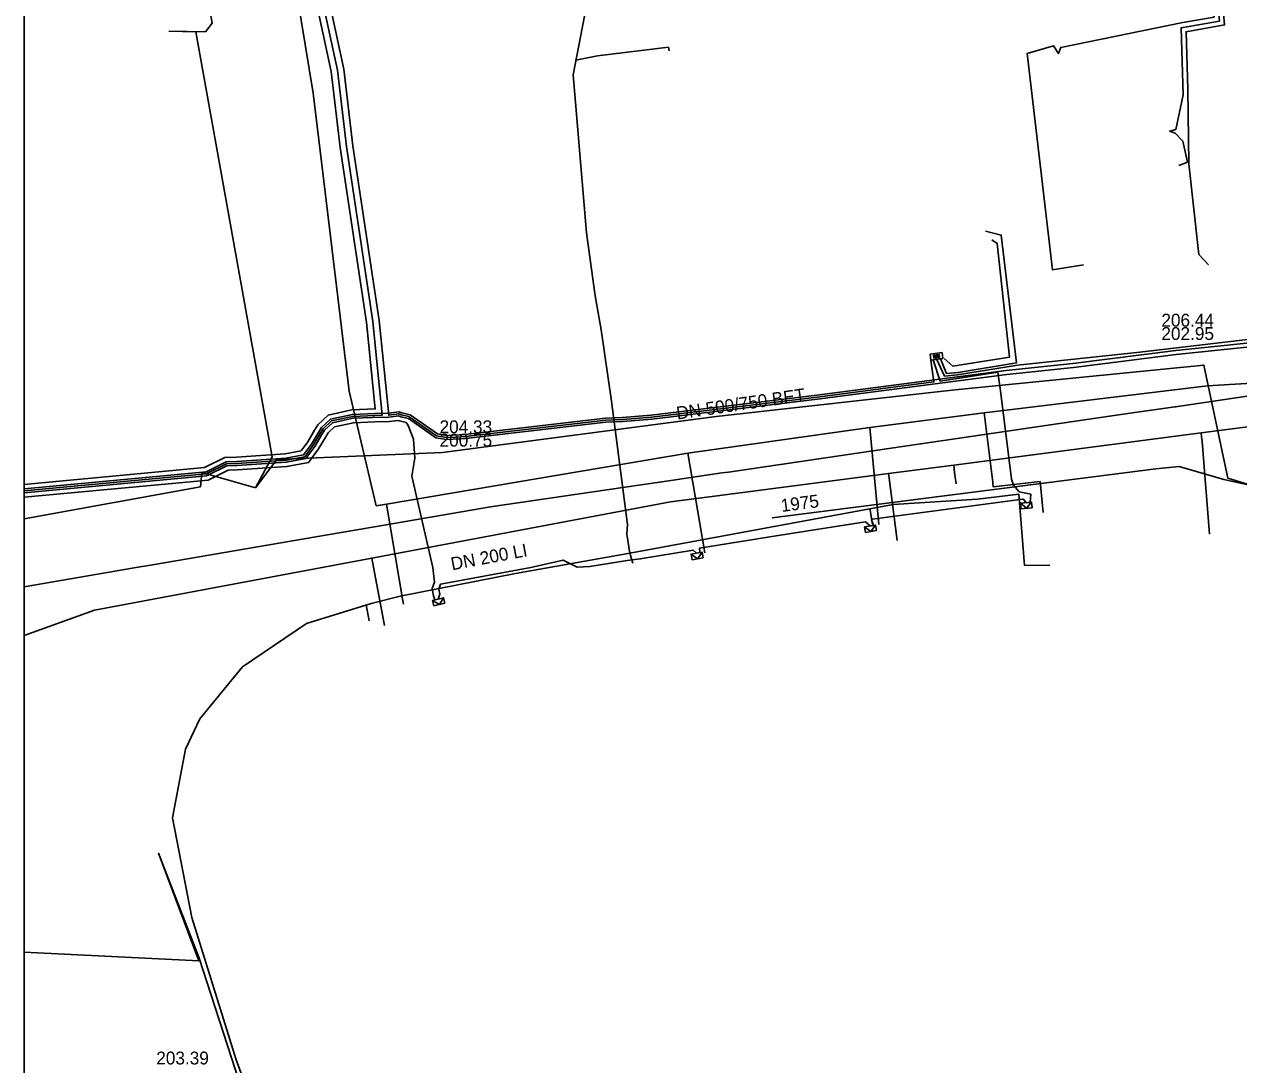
# Model space of a CAD drawing. Extents: x -596024 to -594475, y -1163820 to -1161957.
# Drawn here: x -596024.4 to -595948.9, y -1163073.5 to -1163008.8 of the extents above; entities that cross this region are included whole.
import ezdxf

# ---------------------------------------------------------------- set-up
doc = ezdxf.new("R2010")
doc.units = 0
for name, color, linetype in [('31', 7, 'Continuous'), ('Vrstva 12', 7, 'Continuous'), ('Vrstva 13', 7, 'Continuous'), ('Vrstva 15', 7, 'Continuous'), ('Vrstva 16', 7, 'Continuous'), ('Vrstva 25', 7, 'Continuous'), ('Vrstva 28', 7, 'Continuous'), ('Vrstva 42', 7, 'Continuous'), ('Vrstva 43', 7, 'Continuous'), ('Vrstva 44', 7, 'Continuous'), ('Vrstva 55', 7, 'Continuous'), ('Vrstva 63', 7, 'Continuous'), ('Vrstva 9', 7, 'Continuous')]:
    doc.layers.add(name, color=color, linetype=linetype)

# ---------------------------------------------------------------- blocks, each defined once
blk = doc.blocks.new('NN630')
at = {"layer": '31'}
for points in [[(-0.003, -0.7), (-0.703, 0)], [(-0.703, -0.7), (-0.703, 0), (0.697, 0), (0.697, -0.7)], [(-0.003, -0.7), (0.697, 0)], [(-0.703, -0.7), (0.697, -0.7)]]:
    blk.add_lwpolyline(points, dxfattribs=at)
blk = doc.blocks.new('NN620')
at = {"layer": 'Vrstva 28'}
for points in [[(0.752, 0.004), (-0.748, 0.004)], [(-0.748, 0.004), (-0.748, -0.746)], [(0.752, -0.746), (0.752, 0.004)], [(-0.748, -0.746), (0.752, -0.746)], [(0.368, -0.18), (-0.376, -0.18)], [(-0.376, -0.18), (-0.376, -0.558)], [(-0.376, -0.558), (0.368, -0.558)], [(0.321, -0.227), (-0.329, -0.227)], [(-0.329, -0.227), (-0.329, -0.51)], [(-0.329, -0.51), (0.321, -0.51)], [(0.274, -0.274), (-0.281, -0.274)], [(-0.281, -0.274), (-0.281, -0.463)], [(-0.281, -0.463), (0.274, -0.463)], [(0.227, -0.321), (-0.234, -0.321)], [(-0.234, -0.321), (-0.234, -0.416)], [(-0.234, -0.416), (0.227, -0.416)], [(-0.193, -0.369), (0.185, -0.369)], [(0.227, -0.416), (0.227, -0.321)], [(0.274, -0.463), (0.274, -0.274)], [(0.321, -0.51), (0.321, -0.227)], [(0.368, -0.558), (0.368, -0.18)]]:
    blk.add_lwpolyline(points, dxfattribs=at)

msp = doc.modelspace()

# ---------------------------------------------------------------- linework, layer by layer
at = {"layer": 'Vrstva 13'}
for p, q in [((-595966.6, -1163036.186), (-595966.541, -1163036.643)), ((-595966.541, -1163036.643), (-595966.449, -1163037.349))]:
    msp.add_line(p, q, dxfattribs=at)
for points in [[(-596024.42, -1163046.785), (-596020.059, -1163045.208), (-596002.804, -1163041.968), (-595984.224, -1163038.48), (-595981.79, -1163038.163), (-595970.656, -1163036.714), (-595966.6, -1163036.186), (-595951.216, -1163034.183), (-595944.946, -1163033.367)], [(-595951.216, -1163034.183), (-595951.183, -1163034.434), (-595951.145, -1163034.729), (-595950.693, -1163040.487)], [(-595970.656, -1163036.714), (-595970.62, -1163036.995), (-595970.114, -1163040.875)], [(-596002.804, -1163041.968), (-596002.696, -1163042.542), (-596002.015, -1163046.17)]]:
    msp.add_lwpolyline(points, dxfattribs=at)
at = {"layer": 'Vrstva 16'}
for points in [[(-596007.93, -1163004.08), (-596006.45, -1163013.05), (-596005.85, -1163018.01)], [(-596005.85, -1163018.01), (-596004.2, -1163031.58), (-596002.52, -1163038.72)], [(-596002.52, -1163038.72), (-596001.88, -1163038.62), (-595983.14, -1163035.45), (-595971.81, -1163033.84), (-595964.71, -1163032.93), (-595950.82, -1163031.26), (-595933.58, -1163030.22), (-595931.21, -1163029.96), (-595917.44, -1163031.52)], [(-595964.71, -1163032.93), (-595964.17, -1163037.24)], [(-595971.81, -1163033.84), (-595971.26, -1163039.89)], [(-595983.14, -1163035.45), (-595982.08, -1163041.64)], [(-595964.17, -1163037.24), (-595964.16, -1163037.33), (-595964.14, -1163037.54), (-595961.23, -1163037.21), (-595961.03, -1163039.14)], [(-596001.88, -1163038.62), (-596000.84, -1163044.76)]]:
    msp.add_lwpolyline(points, dxfattribs=at)
at = {"layer": 'Vrstva 25'}
for p, q in [((-595989.347, -1163007.053), (-595990.276, -1163011.905)), ((-595988.751, -1163010.736), (-595984.351, -1163010.187)), ((-595984.351, -1163010.187), (-595984.301, -1163010.413)), ((-595990.105, -1163011.011), (-595988.751, -1163010.736)), ((-595990.276, -1163011.905), (-595989.452, -1163021.745)), ((-595989.452, -1163021.745), (-595988.906, -1163025.66)), ((-595988.906, -1163025.66), (-595988.536, -1163027.784)), ((-595988.536, -1163027.784), (-595987.887, -1163032.216)), ((-595987.887, -1163032.216), (-595986.894, -1163039.883)), ((-595970.377, -1163038.63), (-595965.112, -1163038.316)), ((-595965.112, -1163038.316), (-595962.547, -1163037.99)), ((-595962.547, -1163037.99), (-595962.197, -1163042.44)), ((-595986.74, -1163041.664), (-595970.377, -1163038.63)), ((-595971.645, -1163039.859), (-595971.819, -1163038.897)), ((-595986.894, -1163039.883), (-595986.938, -1163040.478)), ((-595986.938, -1163040.478), (-595986.74, -1163041.664)), ((-595986.74, -1163041.664), (-595993.857, -1163042.933)), ((-595986.74, -1163041.664), (-595986.572, -1163042.284)), ((-595993.857, -1163042.933), (-596001.036, -1163044.341)), ((-595962.197, -1163042.44), (-595960.628, -1163042.419)), ((-596001.036, -1163044.341), (-596002.838, -1163044.793)), ((-596000.835, -1163044.845), (-596000.941, -1163044.322)), ((-596002.838, -1163044.793), (-596006.858, -1163046.041)), ((-596002.957, -1163045.88), (-596003.146, -1163044.889)), ((-596006.858, -1163046.041), (-596010.851, -1163048.745)), ((-596010.851, -1163048.745), (-596013.497, -1163051.962)), ((-596013.497, -1163051.962), (-596014.386, -1163053.865)), ((-596014.386, -1163053.865), (-596015.197, -1163058.134)), ((-596015.197, -1163058.134), (-596013.998, -1163064.332)), ((-596013.998, -1163064.332), (-596011.229, -1163073.182)), ((-596011.229, -1163073.182), (-596007.302, -1163083.82))]:
    msp.add_line(p, q, dxfattribs=at)
msp.add_lwpolyline([(-595989.347, -1163007.053), (-595990.276, -1163011.905), (-595989.452, -1163021.745), (-595988.906, -1163025.66), (-595988.536, -1163027.784), (-595987.887, -1163032.216), (-595986.894, -1163039.883), (-595986.938, -1163040.478), (-595986.74, -1163041.664), (-595993.857, -1163042.933), (-596001.036, -1163044.341), (-596002.838, -1163044.793), (-596006.858, -1163046.041), (-596010.851, -1163048.745), (-596013.497, -1163051.962), (-596014.386, -1163053.865), (-596015.197, -1163058.134), (-596013.998, -1163064.332), (-596011.229, -1163073.182), (-596007.302, -1163083.82)], dxfattribs=at)
at = {"layer": 'Vrstva 42'}
for points in [[(-596001.305, -1163005.871), (-596001.288, -1163005.787), (-596002.874, -1163005.738), (-596003.772, -1163005.922), (-596005.748, -1163006.128), (-596005.988, -1163006.477), (-596005.673, -1163008.176), (-596004.942, -1163011.633), (-596004.378, -1163016.377), (-596002.745, -1163027.259), (-596002.147, -1163033.074), (-596003.986, -1163033.155), (-596005.315, -1163033.442), (-596005.836, -1163033.931), (-596006.012, -1163034.229), (-596006.445, -1163034.955), (-596006.968, -1163035.67), (-596008.133, -1163035.885), (-596011.197, -1163036.087), (-596011.838, -1163036.103), (-596013.098, -1163036.729), (-596024.42, -1163037.79)], [(-595998.135, -1163034.465), (-595998.773, -1163034.37), (-596000.476, -1163033.182), (-596000.489, -1163033.173), (-596000.96, -1163033.06), (-596001.13, -1163032.995), (-596001.743, -1163033.084), (-596002.35, -1163027.193), (-596003.981, -1163016.324), (-596004.546, -1163011.567), (-596005.28, -1163008.098), (-596005.564, -1163006.567), (-596005.523, -1163006.507), (-596003.711, -1163006.318), (-596002.84, -1163006.139), (-596001.851, -1163006.171)], [(-596006.066, -1163008.253), (-596005.338, -1163011.699), (-596004.775, -1163016.43), (-596003.141, -1163027.316), (-596002.588, -1163032.692), (-596004.038, -1163032.756), (-596005.508, -1163033.074), (-596006.151, -1163033.678), (-596006.356, -1163034.024), (-596006.779, -1163034.733), (-596007.196, -1163035.305), (-596008.183, -1163035.487), (-596011.215, -1163035.687), (-596011.937, -1163035.706), (-596013.209, -1163036.338), (-596024.42, -1163037.388)], [(-595967.421, -1163029.587), (-595967.048, -1163030.495), (-595966.319, -1163030.435), (-595962.693, -1163029.819), (-595963.64, -1163021.886), (-595964.632, -1163021.639)], [(-595967.189, -1163029.558), (-595966.658, -1163030.03), (-595963.136, -1163029.483), (-595963.899, -1163022.397), (-595964.223, -1163022.167)], [(-595967.65, -1163029.61), (-595967.179, -1163030.648), (-595966.373, -1163030.564), (-595962.642, -1163029.979), (-595955.21, -1163029.18), (-595948.13, -1163028.36), (-595942.91, -1163027.71), (-595942.67, -1163026.87), (-595942.091, -1163026.74)], [(-596024.42, -1163038.191), (-596012.987, -1163037.12), (-596011.739, -1163036.5), (-596011.179, -1163036.487), (-596008.083, -1163036.282), (-596006.739, -1163036.034), (-596006.111, -1163035.176), (-596005.668, -1163034.433), (-596005.52, -1163034.184), (-596005.122, -1163033.809), (-596003.935, -1163033.553), (-596002.161, -1163033.475), (-596001.876, -1163033.507), (-596001.176, -1163033.406), (-596001.079, -1163033.443), (-596000.668, -1163033.542), (-596000.53, -1163033.726), (-596000.201, -1163034.573), (-596000.134, -1163035.75), (-596000.306, -1163036.867), (-595998.995, -1163042.557), (-595998.903, -1163043.479), (-595999.052, -1163043.873), (-595998.96, -1163044.32), (-595998.873, -1163044.567), (-595998.677, -1163044.522), (-595998.574, -1163044.212), (-595998.638, -1163043.907), (-595998.518, -1163043.592), (-595992.911, -1163042.555), (-595990.9, -1163042.099), (-595990.029, -1163042.529), (-595989.239, -1163042.485), (-595986.906, -1163042.132), (-595986.096, -1163042.021), (-595982.809, -1163041.471), (-595982.592, -1163041.666), (-595982.393, -1163041.634), (-595982.418, -1163041.362), (-595977.64, -1163040.579), (-595972.093, -1163039.719), (-595971.802, -1163039.975), (-595971.6, -1163039.946), (-595971.711, -1163039.596), (-595971.644, -1163039.557), (-595962.316, -1163038.301), (-595962.259, -1163038.313), (-595962.103, -1163038.529), (-595961.843, -1163038.509), (-595961.805, -1163037.995), (-595962.324, -1163037.89), (-595962.526, -1163037.859), (-595962.881, -1163037.439), (-595962.999, -1163037.064), (-595963.682, -1163031.568), (-595963.865, -1163030.406), (-595967.435, -1163030.96), (-595967.871, -1163029.638)], [(-595968.016, -1163029.654), (-595967.836, -1163031.011), (-595975.1, -1163031.955), (-595985.4, -1163033.198), (-595987.189, -1163033.36), (-595988.246, -1163033.396), (-595996.973, -1163034.413), (-595997.592, -1163034.441)], [(-595997.592, -1163034.441), (-595998.135, -1163034.465)]]:
    msp.add_lwpolyline(points, dxfattribs=at)
at = {"layer": 'Vrstva 44'}
for points in [[(-596024.42, -1163037.663), (-596013.109, -1163036.603), (-596011.869, -1163035.979), (-596011.202, -1163035.962), (-596008.149, -1163035.761), (-596007.04, -1163035.557), (-596006.549, -1163034.886), (-596006.119, -1163034.166), (-596005.935, -1163033.852), (-596005.375, -1163033.327), (-596004.002, -1163033.031), (-596002.143, -1163032.949), (-596001.884, -1163032.978), (-596001.116, -1163032.867), (-596000.923, -1163032.94), (-596000.424, -1163033.061), (-595998.724, -1163034.251), (-595998.129, -1163034.34), (-595996.983, -1163034.288), (-595988.255, -1163033.271), (-595987.197, -1163033.235), (-595985.413, -1163033.074), (-595975.116, -1163031.831), (-595963.332, -1163030.301), (-595959.181, -1163029.873), (-595952.781, -1163029.066), (-595939.965, -1163027.723)], [(-596024.42, -1163037.915), (-596013.086, -1163036.852), (-596011.815, -1163036.227), (-596011.19, -1163036.212), (-596008.119, -1163036.009), (-596006.898, -1163035.785), (-596006.341, -1163035.024), (-596005.903, -1163034.294), (-596005.737, -1163034.01), (-596005.255, -1163033.557), (-596003.97, -1163033.279), (-596002.151, -1163033.199), (-596001.88, -1163033.23), (-596001.144, -1163033.123), (-596000.997, -1163033.18), (-596000.528, -1163033.293), (-595998.82, -1163034.489), (-595998.141, -1163034.59), (-595996.963, -1163034.538), (-595988.237, -1163033.521), (-595987.181, -1163033.485), (-595985.387, -1163033.322), (-595975.084, -1163032.079), (-595963.304, -1163030.549), (-595959.153, -1163030.121), (-595952.753, -1163029.314), (-595939.995, -1163027.977)]]:
    msp.add_lwpolyline(points, dxfattribs=at)
at = {"layer": 'Vrstva 55'}
for points in [[(-595994.059, -1163006.613), (-595994.179, -1163005.667), (-595994.31, -1163005.59), (-595997.9, -1163005.7), (-596002.81, -1163005.35), (-596007.97, -1163004.66), (-596012.01, -1163004.24), (-596013, -1163004.78), (-596013.34, -1163005.29), (-596012.74, -1163008.7), (-596013.15, -1163009.24), (-596015.43, -1163009.2)], [(-595950.457, -1163004.452), (-595950.075, -1163008.567), (-595952.452, -1163008.986), (-595952.322, -1163013.167), (-595952.79, -1163015.31), (-595953.16, -1163015.41), (-595952.83, -1163015.54), (-595952.34, -1163016.04), (-595952.06, -1163017.34), (-595952.59, -1163017.55)], [(-595950.158, -1163004.424), (-595949.751, -1163008.814), (-595952.143, -1163009.236), (-595952.026, -1163012.799), (-595951.97, -1163017.45), (-595951.35, -1163023.09), (-595950.76, -1163023.74)], [(-595951.041, -1163004.503), (-595950.743, -1163004.479), (-595950.399, -1163008.32), (-595952.344, -1163008.663), (-595959.93, -1163010.21), (-595960.08, -1163010.595), (-595960.39, -1163010.11), (-595962.04, -1163010.59), (-595960.46, -1163024.04), (-595958.52, -1163023.73)], [(-596015.43, -1163009.2), (-596013.741, -1163009.236), (-596008.99, -1163035.68), (-596010.04, -1163037.6)], [(-596010.04, -1163037.6), (-596008.71, -1163035.83), (-595998.4, -1163035.41), (-595981.37, -1163033.17), (-595966.52, -1163031.51), (-595951.03, -1163029.97), (-595949.55, -1163037), (-595947.99, -1163037.47)], [(-596024.42, -1163039.522), (-596013.468, -1163037.536), (-596013.375, -1163036.646), (-596010.04, -1163037.6)], [(-595947.99, -1163037.47), (-595949.79, -1163037.09), (-595952.57, -1163036.27), (-595954.03, -1163036.42), (-595977.89, -1163039.47)], [(-596024.42, -1163066.479), (-596013.57, -1163067.03), (-596016.079, -1163060.329), (-596013.55, -1163066.86), (-596009.02, -1163080.79), (-596003.82, -1163096.06), (-595991.42, -1163128.644), (-595982.689, -1163163.41), (-595982.3, -1163166.35), (-595978.667, -1163197.753), (-595980.308, -1163202.41), (-595978.69, -1163202.35)]]:
    msp.add_lwpolyline(points, dxfattribs=at)
at = {"layer": 'Vrstva 63'}
msp.add_lwpolyline([(-594475.47, -1163820.23), (-596024.42, -1163820.23), (-596024.42, -1161956.88), (-594475.47, -1161956.88)], close=True, dxfattribs=at)
at = {"layer": 'Vrstva 9'}
for points in [[(-595947.37, -1163031.76), (-595952.804, -1163032.554), (-595952.854, -1163032.561), (-595955.921, -1163033.009), (-595971.346, -1163035.263), (-595980.617, -1163036.618), (-595981.031, -1163036.678), (-595984.463, -1163037.18), (-595986.198, -1163037.434), (-595995.41, -1163038.78)], [(-595995.41, -1163038.78), (-596002.635, -1163040.019), (-596004.704, -1163040.373), (-596016.453, -1163042.388), (-596017.586, -1163042.582), (-596024.42, -1163043.754)]]:
    msp.add_lwpolyline(points, dxfattribs=at)

# ---------------------------------------------------------------- block references
at = {"layer": 'Vrstva 43'}
for name, p, xscale, yscale, rotation in [('NN620', (-595967.65, -1163029.61), 0.5, 0.5000000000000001, -173.00000000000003), ('NN630', (-595962.103, -1163038.529), 0.5, 0.5000000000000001, 6), ('NN630', (-595971.802, -1163039.975), 0.5, 0.5000000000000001, 8.999999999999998), ('NN630', (-595982.592, -1163041.666), 0.49999999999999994, 0.5, 9.999999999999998), ('NN630', (-595998.677, -1163044.522), 0.5, 0.5, 13)]:
    msp.add_blockref(name, p, dxfattribs=dict(at, xscale=xscale, yscale=yscale, rotation=rotation))

# ---------------------------------------------------------------- texts
at = {"layer": 'Vrstva 12'}
for s, p in [('206.44', (-595953.681, -1163027.574)), ('202.95', (-595953.681, -1163028.406)), ('204.33', (-595998.585, -1163034.205)), ('200.75', (-595998.585, -1163035.037)), ('203.39', (-596016.21, -1163073.468))]:
    msp.add_text(s, height=0.8, dxfattribs=at).set_placement(p)
msp.add_text('DN 500/750 BET', height=0.8, rotation=8.30789, dxfattribs=at).set_placement((-595983.791, -1163033.359))
at = {"layer": 'Vrstva 15'}
for s, rotation, p in [('1975', 7.39116, (-595977.306, -1163039.106)), ('DN 200 LI', 10.65701, (-595997.806, -1163042.737))]:
    msp.add_text(s, height=0.8, rotation=rotation, dxfattribs=at).set_placement(p)

doc.saveas('drawing.dxf')
